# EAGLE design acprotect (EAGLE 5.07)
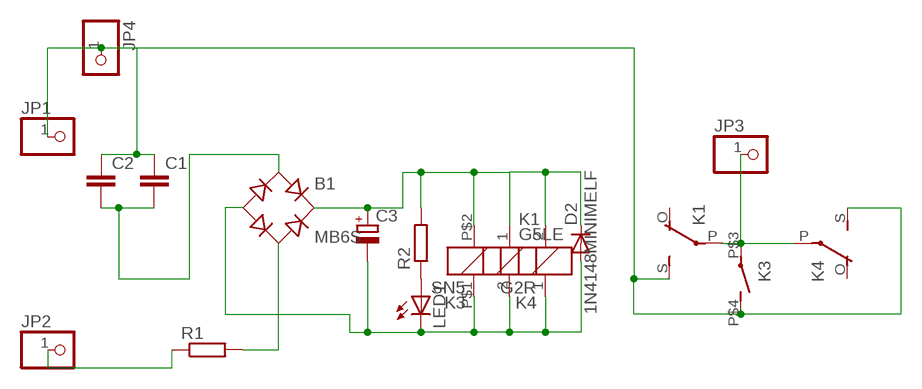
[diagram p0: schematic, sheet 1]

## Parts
B1  MB6S  [SOIC-4]
C1  C-EU102-043X133  [C102-043X133]
C2  C-EU102-043X133  [C102-043X133]
C3  CPOL-EUE2.5-5  [E2,5-5]
D2  1N4148MINIMELF  [MINIMELF]
JP1  PINHD-1X11MM6  [1X1MM8]
JP2  PINHD-1X11MM6  [1X1MM8]
JP3  PINHD-1X11MM6  [1X1MM8]
JP4  PINHD-1X11MM6  [1X1MM8]
K1  G5LE  [G5LE]
K3  SN5  [HU]
K4  G2R  [G2R]
LED1  LEDSMT1206  [1206]
R1  R-EU_0309/10  [0309/10]
R2  R-EU_R0805  [R0805]

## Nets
AC1: C1.1 C2.1 JP1.1 JP4.1 K1.S(2:S) K3.P$4(2:S) K4.S(2:S)
AC2: JP2.1 R1.1
ACOUT: JP3.1 K1.P(2:P) K3.P$3(2:P) K4.P(2:P)
MINUS: B1.- C3.- D2.A K1.2 K3.P$1 K4.1 LED1.C
N$1: LED1.A R2.1
PLUS: B1.+ C3.+ D2.C K1.1 K3.P$2 K4.2 R2.2
RAC1: B1.~1(AC1) C1.2 C2.2
RAC2: B1.~2(AC2) R1.2
Unconnected: K1.O(2:O) K4.O(2:O)

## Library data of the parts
B1 = rectifier:MB*S: Bridge Rectifier Source: http://www.fairchildsemi.com/ds/MB/MB6S.pdf
C1 C2 = rcl:C-EU: CAPACITOR, European symbol
C3 = rcl:CPOL-EU: POLARIZED CAPACITOR, European symbol
D2 = diode-1:1N4148: DIODE
JP1-JP4 = pinhead:PINHD-1X1: PIN HEADER
K1 = relay:G5LE: RELAY 1 x switch, 10 A/120 V AC, 8 A/30 V DC, Omron
K3 = relay:SN*: Slim PCB Relay 1 pole 6 A SCHRACK Source: http://www.schrack.com/.. 5815.pdf
K4 = relay:G2R: RELAY 1 x switch, Omron
LED1 = led:LED: LED
R1 R2 = rcl:R-EU_: RESISTOR, European symbol

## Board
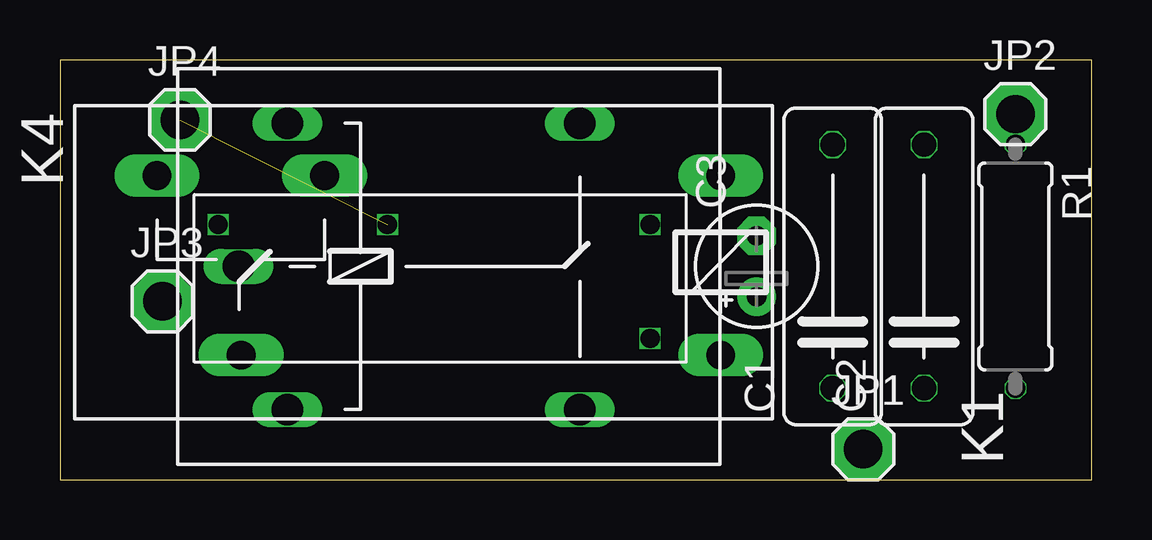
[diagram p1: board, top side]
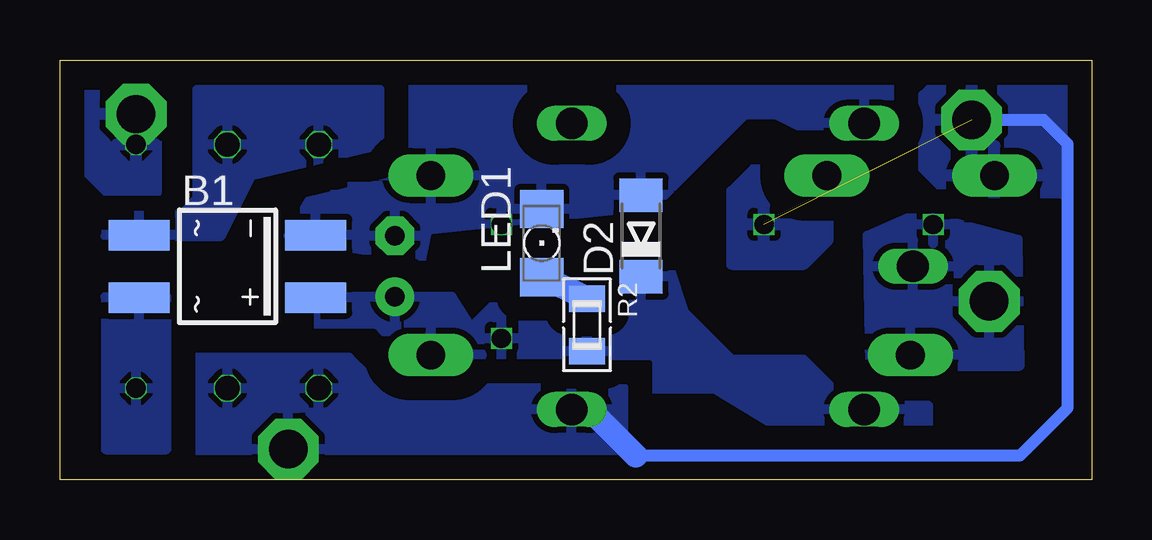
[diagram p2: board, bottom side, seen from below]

Size 43 x 17.5 mm. Coordinates in mm from the lower left corner, seen from the top.
Outline: 0,0 43,0 43,17.5 0,17.5 0,0
Copper layers (1*16): Top 0.035mm / dielectric 1.5mm / Bottom 0.035mm
Design rules "default": minimum track width 10mil, minimum drill 20mil, track to track 8mil, track to pad 8mil, pad to pad 8mil, via to via 8mil, smd to smd 8mil, copper to edge 40mil, drill to drill 8mil, minimum pad ring 1mil, minimum via ring 8mil, stop-mask expansion 4mil, vias tented up to drill 0mil, thermal gap 10mil

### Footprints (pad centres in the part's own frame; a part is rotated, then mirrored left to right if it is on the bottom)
SOIC-4 = smd 1.27 x 2.54: + 1.3,3.685; - -1.3,3.685; ~1 -1.3,-3.685; ~2 1.3,-3.685
C102-043X133 = drill 1.016 octagon: 1 -5.08,0; 2 5.08,0
E2,5-5 = drill 0.813 pad 1.6 round: + -1.27,0 | drill 0.813 pad 1.6 octagon: - 1.27,0
MINIMELF = smd 1.4 x 1.8: A 1.7,0; C -1.7,0
1X1MM8 = drill 1.6 pad 2.54 octagon: 1 0,0
G5LE = drill 1.321 long: 1 -7.493,-5.969; 2 -7.493,5.969; O 4.699,5.969; P -9.525,0; S 4.699,-5.969
HU = drill 0.8 square: P$1 2.25,-9; P$2 -2.5,-9; P$3 2.25,9; P$4 2.25,1.95
G2R = drill 1.2 pad 1.778 long: 1 -2.54,-3.683; 2 -2.54,3.81; O 13.97,-3.683; P 17.45,3.81; S 20.955,-3.683
1206 = smd 1.6 x 1.803: A -1.422,0; C 1.422,0
0309/10 = drill 0.813 octagon: 1 -5.08,0; 2 5.08,0
R0805 = smd 1.1 x 1.5: 1 -1.1,0; 2 1.1,0

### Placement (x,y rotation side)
B1  36.02,8.89 270 bottom
C1  32.21,8.89 90 top
C2  36.02,8.89 90 top
C3  29.04,8.89 90 top
D2  18.78,10.16 90 bottom
JP1  33.48,1.27 0 top
JP2  39.83,15.24 0 top
JP3  4.27,7.43 0 top
JP4  5,15 0 top
K1  16.97,8.89 0 top
K3  15.6,8.39 90 top
K4  25,9 180 top
LED1  22.92,9.86 90 bottom
R1  39.83,8.89 270 top
R2  21.03,6.45 270 bottom

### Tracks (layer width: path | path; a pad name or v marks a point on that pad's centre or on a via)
AC1  (1 unrouted)
  Bottom 0.5: 19,1 3,1 1,3 1,14 2,15 JP4.1
  Bottom 1: K1.S 20.92,2.92 19,1
  pour Bottom (isolate 1, rank 2): 19.51,3.81 29.67,3.81 30.94,5.08 37.29,5.08 37.29,0 20.78,0 19.51,1.27
  pour Bottom (isolate 1): 11,13 14,13 15,12 15,9 12,9 11,10 11,12
  pour Bottom (isolate 1): 1,14 1,17 6,17 7,16 7,13 6,12 1,12
AC2
  pour Bottom (isolate 1): 39,16 42,16 42,13 41,12 39,12
ACOUT
  pour Bottom (isolate 1, rank 2): 3.07,10 7.21,11.1 9.35,10.16 9.25,4.75 3,4.75
MINUS
  pour Bottom (isolate 1, rank 2): 8.08,16.51 29.67,16.51 33.48,10.16 27.94,9.16 27.67,10.43 18.24,11.43 14.43,15.24 13.16,15.24 8.08,12.7
N$1
  Bottom 1: R2.1 LED1.A
PLUS
  pour Bottom (isolate 1, rank 3): 6.81,2.27 6.81,3.08 10.08,3.08 12,5 15,5 17,7 17.62,8.89 23.32,8.89 25.86,6.35 26.67,7.62 32.21,7.62 32.21,5.08 29.67,5.08 28.4,3.81 15.7,3.81 13.16,2.27
RAC1
  pour Bottom (isolate 1): 29.67,16.24 37.29,16.24 37.29,11.71 38,11 41,11 41.1,10.16 36.29,10.16 35.02,12.7 29.67,13.97
RAC2
  pour Bottom: 38.56,7.62 41.1,7.62 41.1,1.27 38.56,1.27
